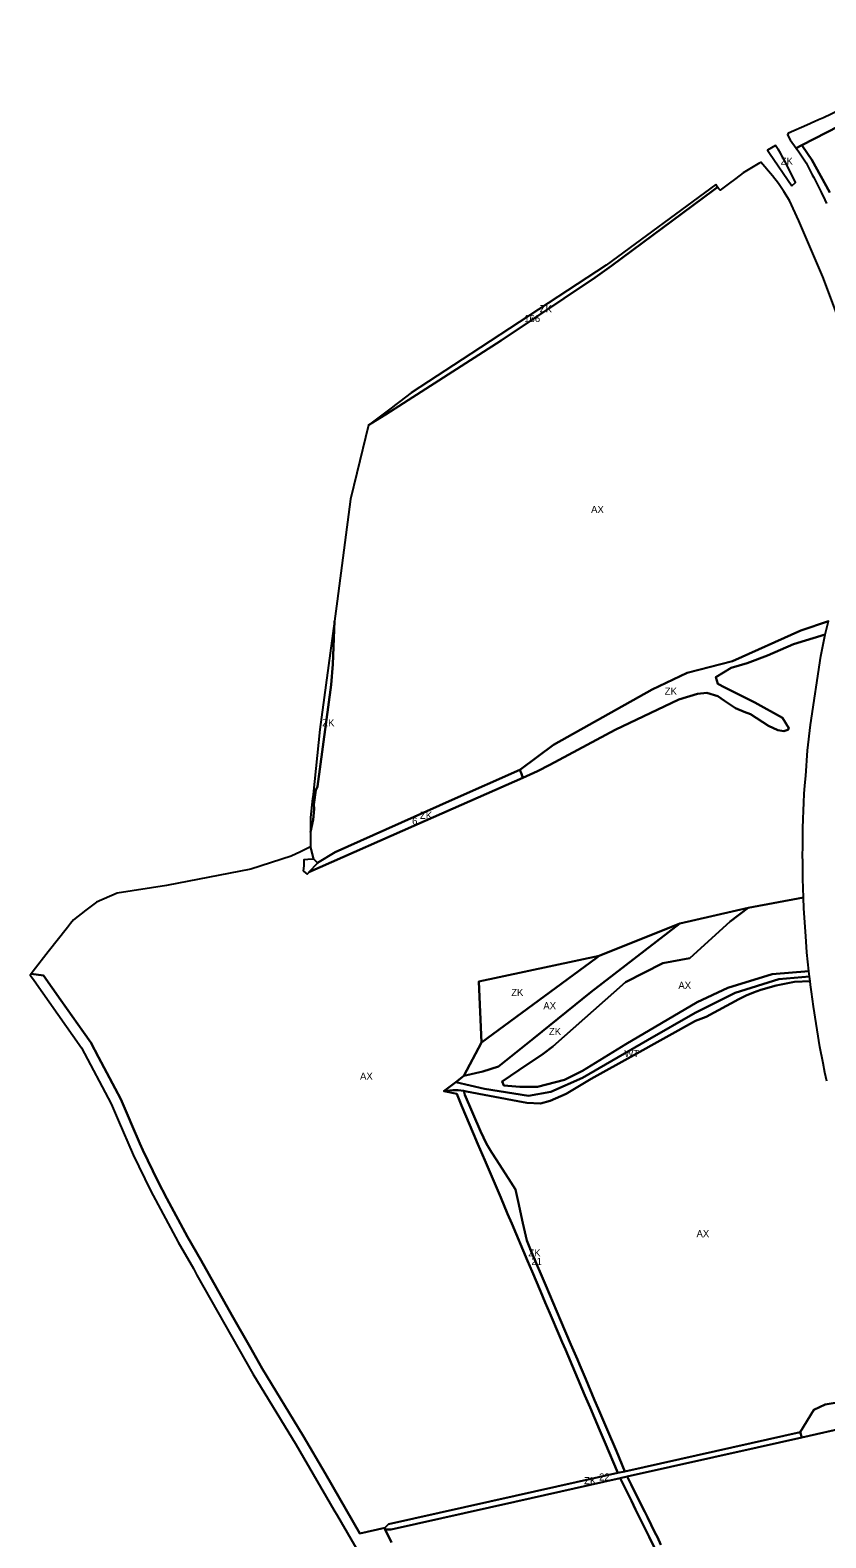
# Model space of a CAD drawing. Extents: x -521939 to -516426, y -1197857 to -1189551.
# Drawn here: x -521939 to -520821, y -1191694 to -1189576 of the extents above; entities that cross this region are included whole.
import ezdxf

# ---------------------------------------------------------------- set-up
doc = ezdxf.new("R2010")
doc.units = 0
for name, color, linetype in [('90640013', 7, 'Continuous'), ('90710013', 7, 'Continuous'), ('90710023', 7, 'Continuous'), ('90750013', 7, 'Continuous'), ('90760013', 7, 'Continuous'), ('ID_navrh', 7, 'Continuous')]:
    doc.layers.add(name, color=color, linetype=linetype)

msp = doc.modelspace()

# ---------------------------------------------------------------- linework, layer by layer
at = {"layer": '90640013'}
msp.add_lwpolyline([(-521357.75, -1191066.04), (-521345.44, -1191064.87), (-521337.72, -1191065.02), (-521330.04, -1191065.83), (-521326.25, -1191066.55), (-521254, -1191080.26), (-521241.52, -1191082.44), (-521222.3, -1191083.69), (-521208.62, -1191080.01), (-521186.27, -1191070.2), (-521151.15, -1191048.86), (-521090.82, -1191015.73), (-521004.39, -1190967.44), (-520989.34, -1190961.96), (-520943.48, -1190936.76), (-520933.42, -1190931.93), (-520923.12, -1190927.67), (-520912.59, -1190923.98), (-520891.13, -1190918), (-520865.37, -1190912.8), (-520843.48, -1190911.63), (-520844.23, -1190905.1), (-520887.29, -1190908.69), (-520948.66, -1190928.12), (-521004.66, -1190956.25), (-521071.65, -1190994.6), (-521163.18, -1191047.27), (-521207.67, -1191067.22), (-521238.87, -1191072.84), (-521301, -1191062.87), (-521341.28, -1191053.41), (-521357.75, -1191066.04)], dxfattribs=at)
at = {"layer": '90710013'}
for points in [[(-520868.84, -1189794.27), (-520863.78, -1189789.93), (-520876.58, -1189763.88), (-520884.99, -1189748.66), (-520888.2, -1189743.1), (-520889, -1189741.91), (-520891.87, -1189737.62), (-520903.31, -1189744.33), (-520900.54, -1189748.5), (-520868.84, -1189794.27)], [(-521511.54, -1190406.16), (-521532.09, -1190558.06), (-521541.77, -1190649.45), (-521542.35, -1190654.87), (-521545.2, -1190681.76), (-521545.21, -1190692.04), (-521545.22, -1190702.33), (-521541.74, -1190684.97), (-521539.95, -1190669.59), (-521540.43, -1190663.29), (-521537.81, -1190643.46), (-521535.27, -1190638.02), (-521516.42, -1190495.63), (-521513.68, -1190466.49), (-521511.54, -1190406.16)], [(-520822, -1190424.77), (-520817.75, -1190406.02), (-520856.45, -1190418.91), (-520952.31, -1190462.12), (-521016.12, -1190478.68), (-521065.06, -1190501.97), (-521203.97, -1190579.5), (-521249.64, -1190614.02), (-521251.04, -1190614.64), (-521249.05, -1190620.36), (-521247.06, -1190626.08), (-521226.27, -1190616.9), (-521208.81, -1190607.77), (-521117.2, -1190558.41), (-521028.03, -1190516.13), (-521001.35, -1190508.14), (-520988.56, -1190506.62), (-520973.08, -1190511.3), (-520963.57, -1190517.89), (-520948.08, -1190528.14), (-520935.85, -1190533.17), (-520927.18, -1190536.7), (-520901.63, -1190552.85), (-520888.76, -1190558.89), (-520880.26, -1190560.73), (-520874.86, -1190558.72), (-520873.05, -1190556.16), (-520882.3, -1190541.54), (-520920.98, -1190520.29), (-520963.26, -1190499.05), (-520972.83, -1190494.21), (-520975.71, -1190484.83), (-520954.38, -1190471.58), (-520931.67, -1190464.89), (-520903.05, -1190454.36), (-520866.64, -1190438.5), (-520822, -1190424.77)], [(-520930.46, -1190808.82), (-521026.22, -1190830.89), (-521151.49, -1190927.2), (-521231.97, -1190992.2), (-521281.09, -1191031.69), (-521303.14, -1191038.45), (-521329.97, -1191044.74), (-521341.28, -1191053.41), (-521301, -1191062.87), (-521238.87, -1191072.84), (-521207.67, -1191067.22), (-521163.18, -1191047.27), (-521071.65, -1190994.6), (-521004.66, -1190956.25), (-520948.66, -1190928.12), (-520887.29, -1190908.69), (-520844.23, -1190905.1), (-520845.07, -1190897.78), (-520896.6, -1190901.88), (-520958.97, -1190920.92), (-521001.86, -1190941.06), (-521102.12, -1191000.34), (-521163.1, -1191037.51), (-521188.22, -1191050.28), (-521226.57, -1191059.93), (-521251.03, -1191059.96), (-521273.53, -1191058.18), (-521276.05, -1191052.73), (-521252.59, -1191036.79), (-521218.27, -1191013.84), (-521204.73, -1191003.3), (-521102.75, -1190913.16), (-521050.15, -1190886.58), (-521012.31, -1190879.41), (-520955.91, -1190827.93), (-520930.46, -1190808.82)], [(-521139.91, -1190876.12), (-521308.8, -1190912.17), (-521304.95, -1190997.73), (-521144.09, -1190879.2), (-521139.91, -1190876.12)], [(-520697.13, -1191510.79), (-520704.46, -1191503.52), (-520712.59, -1191504.94), (-520805.54, -1191503.53), (-520822.16, -1191506.38), (-520838.02, -1191513.71), (-520857.48, -1191545.13), (-520854.89, -1191552.76), (-520788.93, -1191537.99), (-520697.13, -1191510.79)]]:
    msp.add_lwpolyline(points, dxfattribs=at)
at = {"layer": '90710023'}
for points in [[(-520862.97, -1189741.45), (-520855.05, -1189737.39), (-520698.86, -1189657.27), (-520574.91, -1189593.69), (-520584.33, -1189575.74), (-520693.52, -1189631.98), (-520798.15, -1189685.87), (-520813.62, -1189693.84), (-520824.7, -1189698.73), (-520831.59, -1189701.76), (-520832.44, -1189702.13), (-520836.95, -1189704.12), (-520848.1, -1189709.03), (-520873.85, -1189720.38), (-520875.18, -1189722.65), (-520871.46, -1189729.85), (-520862.97, -1189741.45)], [(-520815.47, -1189803.6), (-520840.73, -1189757.97), (-520853.99, -1189738.71), (-520854.52, -1189738.05), (-520855.05, -1189737.39), (-520862.97, -1189741.45)], [(-520862.97, -1189741.45), (-520859.09, -1189746.74), (-520854.49, -1189753.78), (-520848.98, -1189762.26), (-520842.22, -1189775.08), (-520840.25, -1189778.89), (-520838.28, -1189782.7), (-520827.89, -1189803.41), (-520822.82, -1189814.19), (-520820.55, -1189819.14)], [(-520975.8, -1189792.72), (-521129.95, -1189905.7), (-521225, -1189967.98), (-521320.06, -1190030.25), (-521403.82, -1190085.13), (-521419.72, -1190097.27), (-521421.67, -1190098.76), (-521425.29, -1190101.52), (-521432.08, -1190106.71), (-521463.67, -1190130.83), (-521451.59, -1190123.19), (-521439.5, -1190115.54), (-521358.54, -1190063.68), (-521277.58, -1190011.81), (-521145.53, -1189923.09), (-521122.58, -1189906.88), (-520979.19, -1189800.51), (-520973.26, -1189796.11), (-520974.53, -1189794.42), (-520975.8, -1189792.72)], [(-521547.56, -1190758.81), (-521384.14, -1190686.63), (-521247.06, -1190626.08), (-521249.05, -1190620.36), (-521251.04, -1190614.64), (-521346.43, -1190657.14), (-521510.56, -1190730.26), (-521535.38, -1190745.68), (-521536.01, -1190746.36), (-521547.56, -1190758.81)], [(-521440.4, -1191682.13), (-521440.71, -1191679.65), (-521475.77, -1191687.37), (-521524.4, -1191603.79), (-521555.8, -1191550.34), (-521613.32, -1191455.79), (-521630.25, -1191425.87), (-521655.79, -1191380.73), (-521699.07, -1191304.11), (-521718.04, -1191270.95), (-521747.24, -1191216.9), (-521759.83, -1191192.86), (-521780.9, -1191149.22), (-521785.08, -1191139.7), (-521796.68, -1191112.46), (-521800.42, -1191103.83), (-521811.73, -1191077.48), (-521819.76, -1191062.36), (-521842.92, -1191018.58), (-521853.99, -1190997.69), (-521864.2, -1190983.23), (-521895.95, -1190938.24), (-521920.24, -1190903.83), (-521937.86, -1190901.38), (-521939.16, -1190903.04), (-521935.96, -1190907.57), (-521933.74, -1190910.72), (-521866.8, -1191005.56), (-521825.27, -1191083.96), (-521815.35, -1191107.04), (-521794.55, -1191155.45), (-521770.21, -1191205.78), (-521731.15, -1191278.24), (-521709.89, -1191315.39), (-521706.74, -1191320.96), (-521704.75, -1191324.48), (-521626.26, -1191463.39), (-521565.51, -1191562.94), (-521512.5, -1191654.17), (-521507.47, -1191662.82), (-521475.16, -1191718.42)], [(-521357.75, -1191066.04), (-521339.87, -1191070.1), (-521333.03, -1191086.18), (-521316.14, -1191125.96), (-521309.96, -1191140.46), (-521300.29, -1191163.2), (-521277.99, -1191215.69), (-521268.33, -1191238.36), (-521262.5, -1191252.21), (-521240.42, -1191304.4), (-521233.83, -1191319.62), (-521222.21, -1191346.98), (-521215.47, -1191362.92), (-521209, -1191378.24), (-521195.36, -1191410.11), (-521191.65, -1191418.82), (-521187.14, -1191429.23), (-521159.78, -1191493.6), (-521152.49, -1191510.64), (-521146.31, -1191525.29), (-521138.81, -1191542.98), (-521131.85, -1191559.38), (-521113.53, -1191602.49), (-521103.61, -1191600.27), (-521115.6, -1191572.16), (-521128.68, -1191541.41), (-521141.21, -1191511.9), (-521146.18, -1191500.28), (-521158.65, -1191470.84), (-521167.05, -1191451.05), (-521170.39, -1191443.27), (-521179.31, -1191422.24), (-521193.95, -1191387.89), (-521214.55, -1191339.42), (-521234.63, -1191292.32), (-521241.56, -1191275.78), (-521247.03, -1191251.47), (-521253.66, -1191221.09), (-521257.44, -1191204.41), (-521264.02, -1191194.06), (-521283.87, -1191162.75), (-521291.03, -1191151.73), (-521298.06, -1191140.03), (-521306.22, -1191122.56), (-521328.5, -1191071.27), (-521330.04, -1191065.83), (-521337.72, -1191065.02), (-521345.44, -1191064.87), (-521357.75, -1191066.04)], [(-521440.4, -1191682.13), (-521431.76, -1191681.97), (-521258.02, -1191643.05), (-521110.35, -1191609.97), (-521100.31, -1191607.72), (-520917.76, -1191566.84), (-520854.89, -1191552.76), (-520857.48, -1191545.13), (-520926.4, -1191560.57), (-521103.61, -1191600.27), (-521113.53, -1191602.49), (-521257.76, -1191634.79), (-521435.48, -1191674.59), (-521440.71, -1191679.65), (-521440.4, -1191682.13)], [(-521052.87, -1191703.37), (-521058, -1191692.92), (-521061.5, -1191686.09), (-521072.03, -1191664.78), (-521075.75, -1191657.25), (-521083.44, -1191641.83), (-521094.71, -1191618.99), (-521100.31, -1191607.72), (-521110.35, -1191609.97), (-521094.53, -1191641.74), (-521088.54, -1191653.97), (-521082.93, -1191665.23), (-521069.59, -1191692.15), (-521045.95, -1191739.73)], [(-521431.33, -1191700.15), (-521440.4, -1191682.13)]]:
    msp.add_lwpolyline(points, dxfattribs=at)
at = {"layer": '90750013'}
for points in [[(-520698.86, -1189657.27), (-520855.05, -1189737.39), (-520854.52, -1189738.05), (-520853.99, -1189738.71), (-520840.73, -1189757.97), (-520815.47, -1189803.6)], [(-520788.93, -1191537.99), (-520854.89, -1191552.76), (-520917.76, -1191566.84), (-521100.31, -1191607.72), (-521094.71, -1191618.99), (-521083.44, -1191641.83), (-521075.75, -1191657.25), (-521072.03, -1191664.78), (-521061.5, -1191686.09), (-521058, -1191692.92), (-521052.87, -1191703.37)], [(-521045.95, -1191739.73), (-521069.59, -1191692.15), (-521082.93, -1191665.23), (-521088.54, -1191653.97), (-521094.53, -1191641.74), (-521110.35, -1191609.97), (-521258.02, -1191643.05), (-521431.76, -1191681.97), (-521440.4, -1191682.13)], [(-521440.4, -1191682.13), (-521431.33, -1191700.15)]]:
    msp.add_lwpolyline(points, dxfattribs=at)
at = {"layer": '90760013'}
for points in [[(-520803.36, -1189980.65), (-520825.3, -1189922.44), (-520859.28, -1189843.65), (-520872.55, -1189815.19), (-520880.21, -1189802.32), (-520887.88, -1189790.95), (-520896.35, -1189780.16), (-520912.37, -1189761.25), (-520913.92, -1189762.15), (-520925.76, -1189769.09), (-520937.6, -1189776.04), (-520947.93, -1189783.96), (-520958.26, -1189791.88), (-520969.8, -1189800.72), (-520971.53, -1189798.42), (-520973.26, -1189796.11), (-520979.19, -1189800.51), (-521122.58, -1189906.88), (-521145.53, -1189923.09), (-521277.58, -1190011.81), (-521358.54, -1190063.68), (-521439.5, -1190115.54), (-521451.59, -1190123.19), (-521463.67, -1190130.83), (-521480.25, -1190198.3), (-521489.18, -1190234.62), (-521507.71, -1190377.86), (-521511.54, -1190406.16), (-521513.68, -1190466.49), (-521516.42, -1190495.63), (-521535.27, -1190638.02), (-521537.81, -1190643.46), (-521540.43, -1190663.29), (-521539.95, -1190669.59), (-521541.74, -1190684.97), (-521545.22, -1190702.33), (-521545.24, -1190718.06), (-521545.25, -1190723.06), (-521541.21, -1190739.76)], [(-521541.21, -1190739.76), (-521538.36, -1190742.65), (-521535.38, -1190745.68), (-521510.56, -1190730.26), (-521346.43, -1190657.14), (-521251.04, -1190614.64), (-521249.64, -1190614.02), (-521203.97, -1190579.5), (-521065.06, -1190501.97), (-521016.12, -1190478.68), (-520952.31, -1190462.12), (-520856.45, -1190418.91), (-520817.75, -1190406.02)], [(-520930.46, -1190808.82), (-520852.66, -1190794.34), (-520853.48, -1190767.88), (-520853.6, -1190752.22), (-520853.81, -1190743.83), (-520853.87, -1190735.1), (-520853.79, -1190723.11), (-520853.63, -1190713.88), (-520853.44, -1190702.35), (-520853.37, -1190697.08), (-520852.94, -1190683.51), (-520852.56, -1190672.24), (-520852.28, -1190660.73), (-520851.64, -1190648.56), (-520850.63, -1190636.95), (-520849.58, -1190623.3), (-520846.95, -1190587.68), (-520842.97, -1190551.61), (-520828.37, -1190455.3), (-520822, -1190424.77), (-520866.64, -1190438.5), (-520903.05, -1190454.36), (-520931.67, -1190464.89), (-520954.38, -1190471.58), (-520975.71, -1190484.83), (-520972.83, -1190494.21), (-520963.26, -1190499.05), (-520920.98, -1190520.29), (-520882.3, -1190541.54), (-520873.05, -1190556.16), (-520874.86, -1190558.72), (-520880.26, -1190560.73), (-520888.76, -1190558.89), (-520901.63, -1190552.85), (-520927.18, -1190536.7), (-520935.85, -1190533.17), (-520948.08, -1190528.14), (-520963.57, -1190517.89), (-520973.08, -1190511.3), (-520988.56, -1190506.62), (-521001.35, -1190508.14), (-521028.03, -1190516.13), (-521117.2, -1190558.41), (-521208.81, -1190607.77), (-521226.27, -1190616.9), (-521247.06, -1190626.08), (-521384.14, -1190686.63), (-521547.56, -1190758.81), (-521547.57, -1190758.82), (-521549.94, -1190761.37), (-521551.55, -1190760.02), (-521555.31, -1190756.89), (-521554.28, -1190749.81), (-521554.24, -1190747.6), (-521554.15, -1190742.99), (-521554.15, -1190740.73), (-521548.84, -1190740.33), (-521541.21, -1190739.76), (-521545.25, -1190723.06), (-521558.55, -1190729.47), (-521559.5, -1190729.93), (-521572.66, -1190736.27), (-521629.34, -1190754.41), (-521747.69, -1190777.08), (-521816.72, -1190787.89), (-521846.1, -1190800.6), (-521860.95, -1190812.02), (-521878.27, -1190825.33), (-521882.54, -1190830.78), (-521886.8, -1190836.22), (-521913.77, -1190870.64), (-521935.01, -1190897.74), (-521937.86, -1190901.38), (-521920.24, -1190903.83), (-521895.95, -1190938.24), (-521864.2, -1190983.23), (-521853.99, -1190997.69), (-521842.92, -1191018.58), (-521819.76, -1191062.36), (-521811.73, -1191077.48), (-521800.42, -1191103.83), (-521796.68, -1191112.46), (-521785.08, -1191139.7), (-521780.9, -1191149.22), (-521759.83, -1191192.86), (-521747.24, -1191216.9), (-521718.04, -1191270.95), (-521699.07, -1191304.11), (-521655.79, -1191380.73), (-521630.25, -1191425.87), (-521613.32, -1191455.79), (-521555.8, -1191550.34), (-521524.4, -1191603.79), (-521475.77, -1191687.37), (-521440.71, -1191679.65), (-521435.48, -1191674.59), (-521257.76, -1191634.79), (-521113.53, -1191602.49), (-521131.85, -1191559.38), (-521138.81, -1191542.98), (-521146.31, -1191525.29), (-521152.49, -1191510.64), (-521159.78, -1191493.6), (-521187.14, -1191429.23), (-521191.65, -1191418.82), (-521195.36, -1191410.11), (-521209, -1191378.24), (-521215.47, -1191362.92), (-521222.21, -1191346.98), (-521233.83, -1191319.62), (-521240.42, -1191304.4), (-521262.5, -1191252.21), (-521268.33, -1191238.36), (-521277.99, -1191215.69), (-521300.29, -1191163.2), (-521309.96, -1191140.46), (-521316.14, -1191125.96), (-521333.03, -1191086.18), (-521339.87, -1191070.1), (-521357.75, -1191066.04), (-521341.28, -1191053.41), (-521329.97, -1191044.74), (-521304.95, -1190997.73), (-521308.8, -1190912.17), (-521139.91, -1190876.12), (-521026.22, -1190830.89), (-520930.46, -1190808.82)], [(-520930.46, -1190808.82), (-520955.91, -1190827.93), (-521012.31, -1190879.41), (-521050.15, -1190886.58), (-521102.75, -1190913.16), (-521204.73, -1191003.3), (-521218.27, -1191013.84), (-521252.59, -1191036.79), (-521276.05, -1191052.73), (-521273.53, -1191058.18), (-521251.03, -1191059.96), (-521226.57, -1191059.93), (-521188.22, -1191050.28), (-521163.1, -1191037.51), (-521102.12, -1191000.34), (-521001.86, -1190941.06), (-520958.97, -1190920.92), (-520896.6, -1190901.88), (-520845.07, -1190897.78), (-520847.98, -1190871.46), (-520849.49, -1190848.58), (-520852.06, -1190809.58), (-520852.66, -1190794.34), (-520930.46, -1190808.82)], [(-521139.91, -1190876.12), (-521144.09, -1190879.2), (-521304.95, -1190997.73), (-521329.97, -1191044.74), (-521303.14, -1191038.45), (-521281.09, -1191031.69), (-521231.97, -1190992.2), (-521151.49, -1190927.2), (-521026.22, -1190830.89), (-521139.91, -1190876.12)], [(-520820.01, -1191052.05), (-520822.58, -1191039.85), (-520825.08, -1191027.11), (-520829.51, -1191003.76), (-520838.45, -1190947.47), (-520841.49, -1190926.47), (-520842.9, -1190916.64), (-520843.48, -1190911.63), (-520865.37, -1190912.8), (-520891.13, -1190918), (-520912.59, -1190923.98), (-520923.12, -1190927.67), (-520933.42, -1190931.93), (-520943.48, -1190936.76), (-520989.34, -1190961.96), (-521004.39, -1190967.44), (-521090.82, -1191015.73), (-521151.15, -1191048.86), (-521186.27, -1191070.2), (-521208.62, -1191080.01), (-521222.3, -1191083.69), (-521241.52, -1191082.44), (-521254, -1191080.26), (-521326.25, -1191066.55), (-521330.04, -1191065.83), (-521328.5, -1191071.27), (-521306.22, -1191122.56), (-521298.06, -1191140.03), (-521291.03, -1191151.73), (-521283.87, -1191162.75), (-521264.02, -1191194.06), (-521257.44, -1191204.41), (-521253.66, -1191221.09), (-521247.03, -1191251.47), (-521241.56, -1191275.78), (-521234.63, -1191292.32), (-521214.55, -1191339.42), (-521193.95, -1191387.89), (-521179.31, -1191422.24), (-521170.39, -1191443.27), (-521167.05, -1191451.05), (-521158.65, -1191470.84), (-521146.18, -1191500.28), (-521141.21, -1191511.9), (-521128.68, -1191541.41), (-521115.6, -1191572.16), (-521103.61, -1191600.27), (-520926.4, -1191560.57), (-520857.48, -1191545.13), (-520838.02, -1191513.71), (-520822.16, -1191506.38), (-520805.54, -1191503.53)]]:
    msp.add_lwpolyline(points, dxfattribs=at)

# ---------------------------------------------------------------- texts
at = {"layer": '90640013'}
msp.add_text('WT', height=10, rotation=0, dxfattribs=at).set_placement((-521104.31, -1191018.4))
at = {"layer": '90710013'}
for rotation, p in [(360, (-520884.69, -1189764.72)), (0, (-521047.62, -1190509.26)), (0, (-521528.7, -1190553.82)), (360, (-521263.26, -1190932.55)), (0, (-521210.3, -1190987.28))]:
    msp.add_text('ZK', height=10, rotation=rotation, dxfattribs=at).set_placement(p)
at = {"layer": '90710023'}
for rotation, p in [(360, (-521223.25, -1189972)), (360, (-521391.51, -1190683.66)), (0, (-521239.22, -1191298.38)), (0, (-521160.93, -1191618.37))]:
    msp.add_text('ZK', height=10, rotation=rotation, dxfattribs=at).set_placement(p)
at = {"layer": '90760013'}
for rotation, p in [(360, (-521151.04, -1190254.05)), (0, (-521028.42, -1190922.61)), (360, (-521218.19, -1190951.18)), (360, (-521475.7, -1191050.13)), (360, (-521002.92, -1191271.38))]:
    msp.add_text('AX', height=10, rotation=rotation, dxfattribs=at).set_placement(p)
at = {"layer": 'ID_navrh'}
for s, rotation, p in [('166', 360, (-521244.96, -1189985.8)), ('6', 360, (-521402.54, -1190691.8)), ('21', 360, (-521234.98, -1191310.38)), ('22', 0, (-521139.88, -1191613.24))]:
    msp.add_text(s, height=10, rotation=rotation, dxfattribs=at).set_placement(p)

doc.saveas('drawing.dxf')
